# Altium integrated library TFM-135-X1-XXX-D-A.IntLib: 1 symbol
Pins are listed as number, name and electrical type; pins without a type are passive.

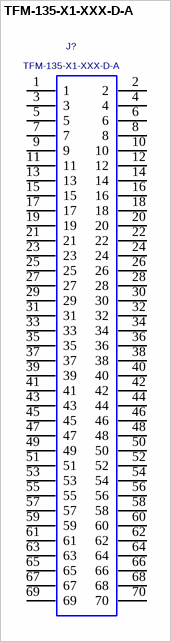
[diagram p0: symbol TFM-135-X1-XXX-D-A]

## TFM-135-X1-XXX-D-A
designator J?
0.050" TERMINAL STRIP, 35 PINS PER ROW.; MANUFACTURER: SAMTEC
footprint TFM-135-X1-XXX-D-A
pins: 1, 2, 3, 4, 5, 6, 7, 8, 9, 10, 11, 12, 13, 14, 15, 16, 17, 18, 19, 20, 21, 22, 23, 24, 25, 26, 27, 28, 29, 30, 31, 32, 33, 34, 35, 36, 37, 38, 39, 40, 41, 42, 43, 44, 45, 46, 47, 48, 49, 50, 51, 52, 53, 54, 55, 56, 57, 58, 59, 60, 61, 62, 63, 64, 65, 66, 67, 68, 69, 70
